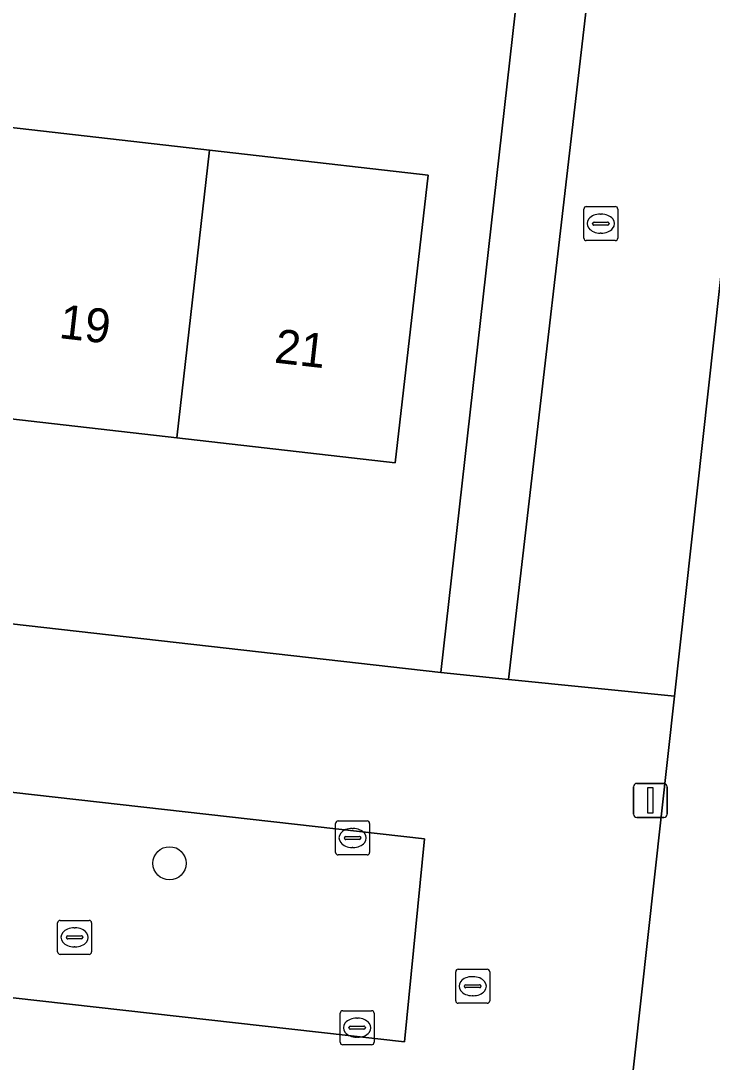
# Model space of a CAD drawing. Extents: x 162082 to 163401, y 388089 to 388636.
# Drawn here: x 162809.05 to 162829.37, y 388400.57 to 388431.17 of the extents above; entities that cross this region are included whole.
import ezdxf

# ---------------------------------------------------------------- set-up
doc = ezdxf.new("R2010")
doc.units = 0
for name, color, linetype in [('IMGEO_Boom', 7, 'Continuous'), ('IMGEO_Erf', 7, 'Continuous'), ('IMGEO_Kolk', 7, 'Continuous'), ('IMGEO_Lichtmast', 7, 'Continuous'), ('IMGEO_Pand', 7, 'Continuous'), ('IMGEO_Pand_nummerreeks', 7, 'Continuous'), ('IMGEO_Parkeervlak_open', 7, 'Continuous'), ('IMGEO_Rijbaan_lokaal_open', 7, 'Continuous'), ('IMGEO_Rioolput', 7, 'Continuous')]:
    doc.layers.add(name, color=color, linetype=linetype)

msp = doc.modelspace()

# ---------------------------------------------------------------- linework, layer by layer
at = {"layer": 'IMGEO_Boom'}
msp.add_circle((162813.423, 388406.414), 0.489, dxfattribs=at)
at = {"layer": 'IMGEO_Erf'}
for points in [[(162833.556, 388459.243), (162828.263, 388411.324), (162826.501, 388395.375)], [(162776.864, 388431.665), (162783.275, 388430.934), (162789.54, 388430.219), (162795.806, 388429.505), (162802.071, 388428.79), (162808.337, 388428.076), (162814.602, 388427.361), (162816.053, 388427.196), (162821.02, 388426.63), (162820.057, 388418.183), (162813.639, 388418.915), (162807.374, 388419.629), (162801.108, 388420.344), (162794.843, 388421.058), (162788.577, 388421.773), (162782.312, 388422.487), (162775.901, 388423.218), (162775.234, 388417.249), (162821.398, 388412.02), (162823.583, 388431.396)]]:
    msp.add_lwpolyline(points, dxfattribs=at)
at = {"layer": 'IMGEO_Kolk'}
for p, q in [((162825.598, 388424.782), (162825.598, 388425.634)), ((162825.673, 388425.708), (162826.525, 388425.708)), ((162826.599, 388425.634), (162826.599, 388424.782)), ((162826.086, 388425.488), (162826.111, 388425.488)), ((162825.857, 388425.202), (162825.857, 388425.214)), ((162826.295, 388425.165), (162825.897, 388425.165)), ((162825.9, 388425.251), (162826.298, 388425.251)), ((162826.341, 388425.214), (162826.341, 388425.202)), ((162826.525, 388424.708), (162825.673, 388424.708)), ((162826.109, 388424.928), (162826.084, 388424.928)), ((162818.303, 388406.734), (162818.303, 388407.586)), ((162818.378, 388407.66), (162819.23, 388407.66)), ((162819.304, 388407.586), (162819.304, 388406.734)), ((162818.791, 388407.44), (162818.816, 388407.44)), ((162818.562, 388407.154), (162818.562, 388407.166)), ((162819, 388407.117), (162818.602, 388407.117)), ((162818.605, 388407.203), (162819.003, 388407.203)), ((162819.046, 388407.166), (162819.046, 388407.154)), ((162819.23, 388406.66), (162818.378, 388406.66)), ((162818.814, 388406.88), (162818.789, 388406.88)), ((162818.512, 388402.083), (162819.364, 388402.083)), ((162818.437, 388401.157), (162818.437, 388402.009)), ((162818.925, 388401.863), (162818.95, 388401.863)), ((162819.438, 388402.009), (162819.438, 388401.157)), ((162818.696, 388401.577), (162818.696, 388401.589)), ((162819.134, 388401.54), (162818.736, 388401.54)), ((162818.739, 388401.626), (162819.137, 388401.626)), ((162819.18, 388401.589), (162819.18, 388401.577)), ((162818.948, 388401.303), (162818.923, 388401.303)), ((162819.364, 388401.083), (162818.512, 388401.083))]:
    msp.add_line(p, q, dxfattribs=at)
for points in [[(162825.598, 388424.782), (162825.598, 388425.634)], [(162825.673, 388425.708), (162826.525, 388425.708)], [(162826.599, 388425.634), (162826.599, 388424.782)], [(162826.525, 388424.708), (162825.673, 388424.708)], [(162818.303, 388406.734), (162818.303, 388407.586)], [(162818.378, 388407.66), (162819.23, 388407.66)], [(162819.304, 388407.586), (162819.304, 388406.734)], [(162819.23, 388406.66), (162818.378, 388406.66)], [(162818.512, 388402.083), (162819.364, 388402.083)], [(162818.437, 388401.157), (162818.437, 388402.009)], [(162819.438, 388402.009), (162819.438, 388401.157)], [(162819.364, 388401.083), (162818.512, 388401.083)]]:
    msp.add_lwpolyline(points, dxfattribs=at)
for centre, radius, start, end in [((162825.675, 388425.632), 0.0765, 91.552, 178.448), ((162825.675, 388425.632), 0.0765, 91.552, 178.448), ((162826.523, 388425.632), 0.0765, 1.552, 88.448), ((162826.523, 388425.632), 0.0765, 1.552, 88.448), ((162825.897, 388425.211), 0.0403, 85.8775, 175.7526), ((162825.894, 388425.201), 0.0366, 178.938, 274.7102), ((162826.298, 388425.208), 0.043, 264.8664, 352.4533), ((162826.302, 388425.213), 0.0386, 1.7309, 96.639), ((162825.675, 388424.784), 0.0765, 181.552, 268.448), ((162825.675, 388424.784), 0.0765, 181.552, 268.448), ((162826.523, 388424.784), 0.0765, 271.552, 358.448), ((162826.523, 388424.784), 0.0765, 271.552, 358.448), ((162818.38, 388407.584), 0.0765, 91.552, 178.448), ((162818.38, 388407.584), 0.0765, 91.552, 178.448), ((162819.228, 388407.584), 0.0765, 1.552, 88.448), ((162819.228, 388407.584), 0.0765, 1.552, 88.448), ((162818.602, 388407.163), 0.0403, 85.8775, 175.7526), ((162818.599, 388407.153), 0.0366, 178.938, 274.7102), ((162819.003, 388407.16), 0.043, 264.8664, 352.4533), ((162819.007, 388407.165), 0.0386, 1.7309, 96.639), ((162818.38, 388406.736), 0.0765, 181.552, 268.448), ((162818.38, 388406.736), 0.0765, 181.552, 268.448), ((162819.228, 388406.736), 0.0765, 271.552, 358.448), ((162819.228, 388406.736), 0.0765, 271.552, 358.448), ((162818.514, 388402.007), 0.0765, 91.552, 178.448), ((162818.514, 388402.007), 0.0765, 91.552, 178.448), ((162819.362, 388402.007), 0.0765, 1.552, 88.448), ((162819.362, 388402.007), 0.0765, 1.552, 88.448), ((162818.736, 388401.586), 0.0403, 85.8775, 175.7526), ((162818.733, 388401.576), 0.0366, 178.938, 274.7102), ((162819.137, 388401.583), 0.043, 264.8664, 352.4533), ((162819.141, 388401.588), 0.0386, 1.7309, 96.639), ((162818.514, 388401.159), 0.0765, 181.552, 268.448), ((162818.514, 388401.159), 0.0765, 181.552, 268.448), ((162819.362, 388401.159), 0.0765, 271.552, 358.448), ((162819.362, 388401.159), 0.0765, 271.552, 358.448)]:
    msp.add_arc(centre, radius, start, end, dxfattribs=at)
for centre, major_axis, ratio, start_param, end_param in [((162826.085, 388425.208), (-0.387, 0.002), 0.722429, 4.712389, 7.853982), ((162826.11, 388425.208), (-0.39, 0.002), 0.717154, 1.570796, 4.712389), ((162818.79, 388407.16), (-0.387, 0.002), 0.722429, 4.712389, 7.853982), ((162818.815, 388407.16), (-0.39, 0.002), 0.717154, 1.570796, 4.712389), ((162818.924, 388401.583), (-0.387, 0.002), 0.722429, 4.712389, 7.853982), ((162818.949, 388401.583), (-0.39, 0.002), 0.717154, 1.570796, 4.712389)]:
    msp.add_ellipse(centre, major_axis=major_axis, ratio=ratio, start_param=start_param, end_param=end_param, dxfattribs=at)
at = {"layer": 'IMGEO_Lichtmast'}
for p, q in [((162827.061, 388407.862), (162827.061, 388408.662)), ((162827.061, 388408.662), (162827.061, 388407.862)), ((162827.161, 388408.762), (162827.951, 388408.762)), ((162827.951, 388408.762), (162827.161, 388408.762)), ((162828.051, 388408.662), (162828.051, 388407.862)), ((162828.051, 388407.862), (162828.051, 388408.662)), ((162827.951, 388407.762), (162827.161, 388407.762)), ((162827.161, 388407.762), (162827.951, 388407.762))]:
    msp.add_line(p, q, dxfattribs=at)
msp.add_lwpolyline([(162827.481, 388408.637), (162827.631, 388408.637), (162827.631, 388407.887), (162827.481, 388407.887), (162827.481, 388408.637)], dxfattribs=at)
for centre, start, end in [((162827.161, 388408.662), 90, 180), ((162827.161, 388408.662), 90, 180), ((162827.951, 388408.662), 0, 90), ((162827.951, 388408.662), 360, 90), ((162827.161, 388407.862), 180, 270), ((162827.161, 388407.862), 180, 270), ((162827.951, 388407.862), 270, 0), ((162827.951, 388407.862), 270, 0)]:
    msp.add_arc(centre, 0.1, start, end, dxfattribs=at)
at = {"layer": 'IMGEO_Pand'}
for points in [[(162814.602, 388427.361), (162808.337, 388428.076), (162807.374, 388419.629), (162813.639, 388418.915)], [(162814.602, 388427.361), (162813.639, 388418.915), (162820.057, 388418.183), (162821.02, 388426.63), (162816.053, 388427.196)]]:
    msp.add_lwpolyline(points, close=True, dxfattribs=at)
at = {"layer": 'IMGEO_Parkeervlak_open'}
msp.add_lwpolyline([(162823.583, 388431.396), (162821.398, 388412.02), (162823.389, 388411.818), (162825.938, 388433.88)], dxfattribs=at)
msp.add_lwpolyline([(162820.326, 388401.167), (162820.916, 388407.138), (162781.393, 388411.586), (162780.76, 388405.619)], close=True, dxfattribs=at)
at = {"layer": 'IMGEO_Rijbaan_lokaal_open'}
for points in [[(162833.556, 388459.243), (162828.6, 388459.865), (162826.936, 388442.688), (162826.934, 388442.495), (162826.517, 388438.76), (162826.395, 388437.963), (162825.974, 388434.188), (162825.938, 388433.88), (162823.389, 388411.818), (162828.263, 388411.324)], [(162828.263, 388411.324), (162823.389, 388411.818), (162821.398, 388412.02), (162775.234, 388417.249), (162773.715, 388417.421), (162773.687, 388416.866), (162773.101, 388411.727), (162772.564, 388407.015), (162772.4, 388405.427), (162772.078, 388401.51), (162773.511, 388401.349), (162798.904, 388398.502), (162803.622, 388397.973), (162808.779, 388397.395), (162813.768, 388396.836), (162826.501, 388395.375)], [(162780.76, 388405.619), (162781.393, 388411.586), (162820.916, 388407.138), (162820.326, 388401.167)]]:
    msp.add_lwpolyline(points, close=True, dxfattribs=at)
at = {"layer": 'IMGEO_Rioolput'}
for p, q in [((162810.133, 388403.812), (162810.133, 388404.664)), ((162810.208, 388404.738), (162811.06, 388404.738)), ((162810.621, 388404.518), (162810.646, 388404.518)), ((162811.134, 388404.664), (162811.134, 388403.812)), ((162810.392, 388404.232), (162810.392, 388404.244)), ((162810.83, 388404.195), (162810.432, 388404.195)), ((162810.435, 388404.281), (162810.833, 388404.281)), ((162810.876, 388404.244), (162810.876, 388404.232)), ((162810.644, 388403.958), (162810.619, 388403.958)), ((162811.06, 388403.738), (162810.208, 388403.738)), ((162821.908, 388403.304), (162822.76, 388403.304)), ((162821.833, 388402.378), (162821.833, 388403.23)), ((162822.321, 388403.084), (162822.346, 388403.084)), ((162822.834, 388403.23), (162822.834, 388402.378)), ((162822.092, 388402.798), (162822.092, 388402.81)), ((162822.53, 388402.761), (162822.132, 388402.761)), ((162822.135, 388402.847), (162822.533, 388402.847)), ((162822.576, 388402.81), (162822.576, 388402.798)), ((162822.344, 388402.524), (162822.319, 388402.524)), ((162822.76, 388402.304), (162821.908, 388402.304))]:
    msp.add_line(p, q, dxfattribs=at)
for points in [[(162810.133, 388403.812), (162810.133, 388404.664)], [(162810.208, 388404.738), (162811.06, 388404.738)], [(162811.134, 388404.664), (162811.134, 388403.812)], [(162811.06, 388403.738), (162810.208, 388403.738)], [(162821.908, 388403.304), (162822.76, 388403.304)], [(162821.833, 388402.378), (162821.833, 388403.23)], [(162822.834, 388403.23), (162822.834, 388402.378)], [(162822.76, 388402.304), (162821.908, 388402.304)]]:
    msp.add_lwpolyline(points, dxfattribs=at)
for centre, radius, start, end in [((162810.21, 388404.662), 0.0765, 91.552, 178.448), ((162810.21, 388404.662), 0.0765, 91.552, 178.448), ((162811.058, 388404.662), 0.0765, 1.552, 88.448), ((162811.058, 388404.662), 0.0765, 1.552, 88.448), ((162810.432, 388404.241), 0.0403, 85.8775, 175.7526), ((162810.429, 388404.231), 0.0366, 178.938, 274.7102), ((162810.833, 388404.238), 0.043, 264.8664, 352.4533), ((162810.837, 388404.243), 0.0386, 1.7309, 96.639), ((162810.21, 388403.814), 0.0765, 181.552, 268.448), ((162810.21, 388403.814), 0.0765, 181.552, 268.448), ((162811.058, 388403.814), 0.0765, 271.552, 358.448), ((162811.058, 388403.814), 0.0765, 271.552, 358.448), ((162821.91, 388403.228), 0.0765, 91.552, 178.448), ((162821.91, 388403.228), 0.0765, 91.552, 178.448), ((162822.758, 388403.228), 0.0765, 1.552, 88.448), ((162822.758, 388403.228), 0.0765, 1.552, 88.448), ((162822.132, 388402.807), 0.0403, 85.8775, 175.7526), ((162822.129, 388402.797), 0.0366, 178.938, 274.7102), ((162822.533, 388402.804), 0.043, 264.8664, 352.4533), ((162822.537, 388402.809), 0.0386, 1.7309, 96.639), ((162821.91, 388402.38), 0.0765, 181.552, 268.448), ((162821.91, 388402.38), 0.0765, 181.552, 268.448), ((162822.758, 388402.38), 0.0765, 271.552, 358.448), ((162822.758, 388402.38), 0.0765, 271.552, 358.448)]:
    msp.add_arc(centre, radius, start, end, dxfattribs=at)
for centre, major_axis, ratio, start_param, end_param in [((162810.62, 388404.238), (-0.387, 0.002), 0.722429, 4.712389, 7.853982), ((162810.645, 388404.238), (-0.39, 0.002), 0.717154, 1.570796, 4.712389), ((162822.32, 388402.804), (-0.387, 0.002), 0.722429, 4.712389, 7.853982), ((162822.345, 388402.804), (-0.39, 0.002), 0.717154, 1.570796, 4.712389)]:
    msp.add_ellipse(centre, major_axis=major_axis, ratio=ratio, start_param=start_param, end_param=end_param, dxfattribs=at)

# ---------------------------------------------------------------- texts
at = {"layer": 'IMGEO_Pand_nummerreeks'}
for s, p in [('19', (162810.15, 388421.848)), ('21', (162816.48, 388421.127))]:
    msp.add_text(s, height=1, rotation=353.4948, dxfattribs=at).set_placement(p)

doc.saveas('drawing.dxf')
